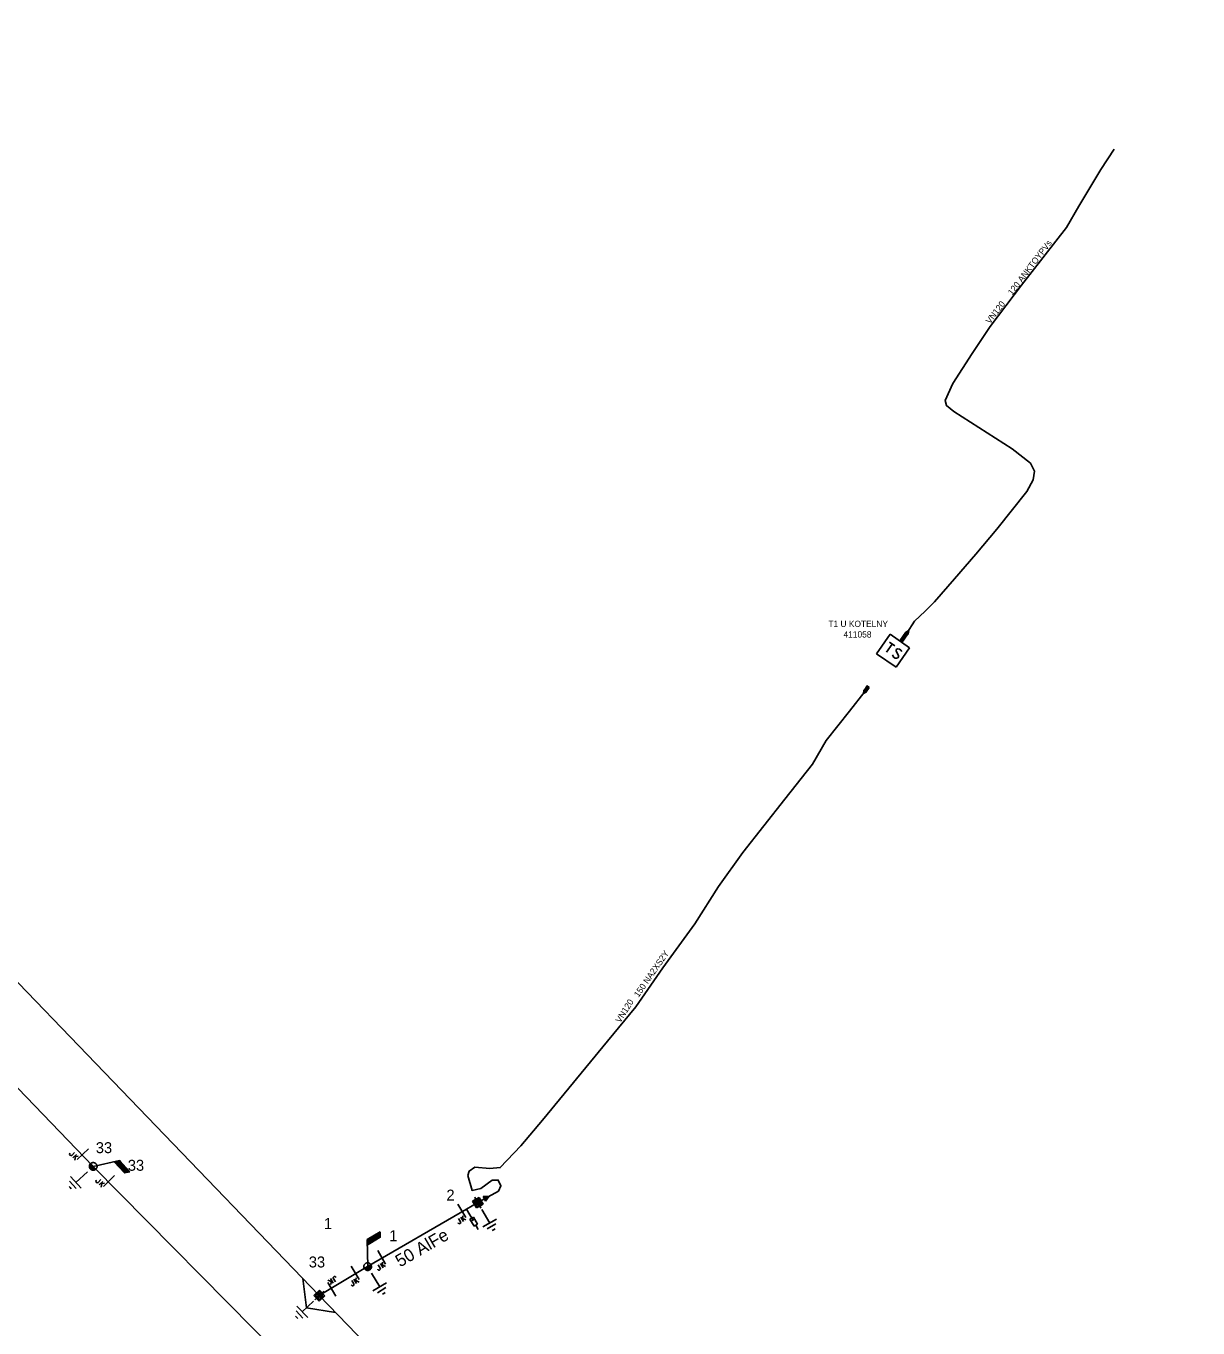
# Model space of a CAD drawing. Extents: x -540340 to -537226, y -1183949 to -1180375.
# Drawn here: x -538950.1 to -538763.3, y -1181558.8 to -1181351.3 of the extents above; entities that cross this region are included whole.
import ezdxf

# ---------------------------------------------------------------- set-up
doc = ezdxf.new("R2010")
doc.units = 0
for name, color, linetype in [('Default', 7, 'Continuous'), ('Vrstva 1', 7, 'Continuous'), ('Vrstva 11', 7, 'Continuous'), ('Vrstva 12', 7, 'Continuous'), ('Vrstva 13', 7, 'Continuous'), ('Vrstva 14', 7, 'Continuous'), ('Vrstva 15', 7, 'Continuous'), ('Vrstva 16', 7, 'Continuous'), ('Vrstva 18', 7, 'Continuous'), ('Vrstva 19', 7, 'Continuous'), ('Vrstva 2', 7, 'Continuous'), ('Vrstva 20', 7, 'Continuous'), ('Vrstva 25', 7, 'Continuous'), ('Vrstva 26', 7, 'Continuous'), ('Vrstva 27', 7, 'Continuous'), ('Vrstva 4', 7, 'Continuous'), ('Vrstva 5', 7, 'Continuous'), ('Vrstva 52', 7, 'Continuous'), ('Vrstva 53', 7, 'Continuous'), ('Vrstva 6', 7, 'Continuous'), ('Vrstva 7', 7, 'Continuous')]:
    doc.layers.add(name, color=color, linetype=linetype)

# ---------------------------------------------------------------- blocks, each defined once
blk = doc.blocks.new('VN840')
at = {"layer": 'Vrstva 15'}
for points in [[(-0.01, 1.41), (-0.01, -1.09)], [(-1.51, -1.24), (-1.51, -1.15)], [(-1.48, -1.35), (-1.51, -1.24)], [(-1.33, -1.42), (-1.48, -1.35)], [(-1.27, -1.42), (-1.33, -1.42)], [(-1.13, -1.35), (-1.27, -1.42)], [(-1.09, -1.24), (-1.13, -1.35)], [(-1.09, -0.59), (-1.09, -1.24)], [(-0.68, -0.59), (-0.68, -1.42)], [(-0.68, -1.11), (-0.27, -0.59)], [(-0.54, -0.94), (-0.2, -1.42)]]:
    blk.add_lwpolyline(points, dxfattribs=at)
blk = doc.blocks.new('VN860')
at = {"layer": 'Vrstva 15'}
for points in [[(-3.74, 0), (0.01, 2.82)], [(0.01, 2.82), (3.76, 0)]]:
    blk.add_lwpolyline(points, dxfattribs=at)
blk = doc.blocks.new('VN440')
at = {"layer": 'Vrstva 2'}
for points in [[(1.22, 0), (1.21, 0.13), (1.19, 0.25), (1.16, 0.38), (1.11, 0.5), (1.05, 0.61), (0.98, 0.72), (0.9, 0.82), (0.81, 0.91), (0.71, 0.99), (0.6, 1.06), (0.49, 1.12), (0.37, 1.16), (0.25, 1.2), (0.12, 1.22), (-0.01, 1.22), (-0.14, 1.22), (-0.26, 1.2), (-0.39, 1.16), (-0.51, 1.12), (-0.62, 1.06), (-0.73, 0.99), (-0.83, 0.91), (-0.92, 0.82), (-1, 0.72), (-1.07, 0.61), (-1.13, 0.5), (-1.18, 0.38), (-1.21, 0.25), (-1.23, 0.13), (-1.24, 0), (-1.23, -0.13), (-1.21, -0.26), (-1.18, -0.38), (-1.13, -0.5), (-1.07, -0.62), (-1, -0.73), (-0.92, -0.83), (-0.83, -0.92), (-0.73, -1), (-0.62, -1.07), (-0.51, -1.13), (-0.39, -1.17), (-0.26, -1.2), (-0.14, -1.23), (-0.01, -1.23), (0.12, -1.23), (0.25, -1.2), (0.37, -1.17), (0.49, -1.13), (0.6, -1.07), (0.71, -1), (0.81, -0.92), (0.9, -0.83), (0.98, -0.73), (1.05, -0.62), (1.11, -0.5), (1.16, -0.38), (1.19, -0.26), (1.21, -0.13), (1.22, 0)], [(-1.24, 0), (1.22, 0)], [(-1.18, -0.34), (1.1, -0.34)], [(-1.01, -0.63), (0.97, -0.63)], [(-0.74, -0.92), (0.68, -0.92)]]:
    blk.add_lwpolyline(points, dxfattribs=at)
blk = doc.blocks.new('VN870')
at = {"layer": 'Vrstva 4'}
for points in [[(0, -0.25), (0.5, 0), (0, 0.25), (-0.5, 0), (0, -0.25)], [(0.37, 0), (0, 0.19), (-0.36, 0), (0, -0.19), (0.37, 0)], [(0.24, 0), (0, 0.12), (-0.25, 0), (0, -0.12), (0.24, 0)], [(0.12, 0), (0, 0.06), (-0.13, 0), (0, -0.06), (0.12, 0)]]:
    blk.add_lwpolyline(points, dxfattribs=at)
blk = doc.blocks.new('VN890')
at = {"layer": 'Vrstva 4'}
for points in [[(-0.41, 0.41), (0.41, 0)], [(-0.41, -0.41), (-0.41, 0.41)], [(0.41, 0), (-0.41, -0.41)], [(-0.34, 0.31), (0.27, 0), (-0.34, -0.3), (-0.34, 0.31)], [(-0.26, 0.2), (0.1, 0), (-0.26, -0.18), (-0.26, 0.2)], [(-0.19, 0.09), (-0.04, 0), (-0.19, -0.08), (-0.19, 0.09)], [(-0.16, -0.01), (-0.16, 0.03), (-0.13, 0.01), (-0.16, -0.01)]]:
    blk.add_lwpolyline(points, dxfattribs=at)
blk = doc.blocks.new('VN820')
at = {"layer": 'Vrstva 13'}
for points in [[(0, 0), (0, -2.1)], [(-0.32, -1.63), (0.34, -1.63)], [(-0.32, -2.95), (-0.32, -1.63)], [(0, -2.1), (-0.12, -1.86)], [(0, -2.1), (0.12, -1.86)], [(0.34, -1.63), (0.34, -2.95)], [(0.34, -2.95), (-0.32, -2.95)], [(0, -2.95), (0, -3.75)]]:
    blk.add_lwpolyline(points, dxfattribs=at)
blk = doc.blocks.new('VN810')
at = {"layer": 'Vrstva 14'}
for points in [[(0, -1.25), (0, -3.75)], [(1.25, -3.75), (-1.25, -3.75)], [(0.77, -4.37), (-0.8, -4.37)], [(0, -5), (-0.25, -5)], [(0.27, -5), (0, -5)]]:
    blk.add_lwpolyline(points, dxfattribs=at)
blk = doc.blocks.new('VN640')
at = {"layer": 'Vrstva 6'}
for points in [[(-1.89, 1.89), (1.89, 1.89)], [(-1.89, -1.89), (-1.89, 1.89)], [(-1.26, 0.79), (-0.22, 0.79)], [(-0.73, 0.79), (-0.73, -0.79)], [(1.2, 0.66), (0.94, 0.79), (0.66, 0.79), (0.41, 0.66), (0.28, 0.47), (0.28, 0.41), (0.41, 0.22), (1.13, -0.16), (1.26, -0.32), (1.26, -0.47), (1.13, -0.66), (0.91, -0.79), (0.63, -0.79), (0.5, -0.73), (0.28, -0.6)], [(1.89, 1.89), (1.89, -1.89)], [(1.89, -1.89), (-1.89, -1.89)]]:
    blk.add_lwpolyline(points, dxfattribs=at)
blk = doc.blocks.new('VN001')
at = {"layer": 'Default'}
for p, q in [((1.73, 3.03), (4.14, 3.03)), ((1.76, 3.08), (4.17, 3.08)), ((1.79, 3.13), (4.2, 3.13)), ((1.82, 3.18), (4.23, 3.18)), ((1.85, 3.23), (4.26, 3.23)), ((1.87, 3.28), (4.29, 3.28)), ((1.9, 3.33), (4.32, 3.33)), ((1.93, 3.38), (4.35, 3.38)), ((1.96, 3.43), (4.37, 3.43)), ((1.99, 3.48), (4.4, 3.48)), ((2.02, 3.53), (4.43, 3.53)), ((2.05, 3.58), (4.46, 3.58)), ((2.07, 3.63), (4.49, 3.63)), ((2.1, 3.68), (4.52, 3.68)), ((2.13, 3.73), (2.54, 3.73))]:
    blk.add_line(p, q, dxfattribs=at)
blk.add_lwpolyline([(2.13, 3.73), (0, 0)], dxfattribs=at)
blk.add_lwpolyline([(4.55, 3.73), (2.13, 3.73), (1.7, 2.98), (4.12, 2.99)], close=True, dxfattribs=at)
blk = doc.blocks.new('VN470')
at = {"layer": 'Vrstva 2'}
for points in [[(-1.23, 1.22), (1.23, 1.22)], [(-1.23, -1.23), (-1.23, 1.22)], [(-0.92, 0.9), (0.92, 0.9)], [(-0.92, -0.95), (-0.92, 0.9)], [(-0.61, 0.61), (0.61, 0.61)], [(-0.61, -0.62), (-0.61, 0.61)], [(-0.31, -0.27), (-0.31, 0.34)], [(-0.31, 0.34), (0.31, 0.34)], [(0, 1.22), (0, 1.97)], [(0.31, 0.34), (0.31, -0.27)], [(0.61, 0.61), (0.61, -0.62)], [(0.92, 0.9), (0.92, -0.95)], [(1.23, 1.22), (1.23, -1.23)], [(1.23, -1.23), (-1.23, -1.23)], [(0.92, -0.95), (-0.92, -0.95)], [(0.61, -0.62), (-0.61, -0.62)], [(0.31, -0.27), (-0.31, -0.27)], [(0, -1.23), (0, -1.98)]]:
    blk.add_lwpolyline(points, dxfattribs=at)

msp = doc.modelspace()

# ---------------------------------------------------------------- linework, layer by layer
at = {"layer": 'Vrstva 1'}
for points in [[(-539146.14, -1181230.44), (-539111.36, -1181296.54), (-539067.4, -1181383.96), (-539015.51, -1181436.9), (-538960.93, -1181493.88), (-538903.36, -1181553.62)], [(-538939.39, -1181533.04), (-538968.73, -1181502.62), (-539023.69, -1181446.75), (-539076.4, -1181392.09), (-539119.1, -1181309.84), (-539155.83, -1181236.81)], [(-538763.29, -1181645.65), (-538807.89, -1181632.52), (-538857.34, -1181618.16), (-538909.5, -1181563.31), (-538939.39, -1181533.04)], [(-538903.36, -1181553.62), (-538849.02, -1181609.88), (-538806.29, -1181621.96)]]:
    msp.add_lwpolyline(points, dxfattribs=at)
at = {"layer": 'Vrstva 20'}
for points in [[(-538809.52, -1181448.13), (-538810.52, -1181449.52), (-538810.84, -1181449.28), (-538809.84, -1181447.89)], [(-538815.7, -1181456.67), (-538816.16, -1181457.37), (-538816.5, -1181457.15), (-538816.04, -1181456.45)]]:
    msp.add_lwpolyline(points, close=True, dxfattribs=at)
at = {"layer": 'Vrstva 5'}
for points in [[(-538809.68, -1181448.01), (-538808.46, -1181446.13), (-538806.8, -1181444.55), (-538805.27, -1181443.02), (-538802.1, -1181439.35), (-538798.72, -1181435.42), (-538795.33, -1181431.47), (-538790.58, -1181425.45), (-538789.58, -1181423.57), (-538789.33, -1181422.23), (-538790, -1181420.95), (-538792.9, -1181418.66), (-538802.22, -1181412.68), (-538803.36, -1181411.75), (-538803.6, -1181410.94), (-538802.39, -1181408.22), (-538799.31, -1181403.45), (-538796.4, -1181399.13), (-538791.4, -1181392.56), (-538784.22, -1181383.36), (-538782.29, -1181379.95), (-538778.77, -1181374.11), (-538776.66, -1181370.87)], [(-538810.68, -1181449.4), (-538809.68, -1181448.01)], [(-538815.87, -1181456.56), (-538816.33, -1181457.26)], [(-538816.33, -1181457.26), (-538818.83, -1181460.47), (-538822.55, -1181465.15), (-538824.73, -1181468.93), (-538829.15, -1181474.51), (-538835.86, -1181482.98), (-538839.73, -1181488.4), (-538843.49, -1181494.37), (-538848.59, -1181501.4), (-538852.89, -1181507.61), (-538857.39, -1181513.06), (-538867.76, -1181525.68), (-538871.21, -1181529.77), (-538874.52, -1181533.23), (-538876.19, -1181533.36), (-538878.57, -1181533.16), (-538879.44, -1181533.78), (-538879.66, -1181534.48), (-538878.99, -1181536.85), (-538877.61, -1181536.54), (-538875.79, -1181535.2), (-538874.82, -1181535.22), (-538874.4, -1181536.13), (-538874.8, -1181536.98), (-538878.07, -1181538.81)]]:
    msp.add_lwpolyline(points, dxfattribs=at)
at = {"layer": 'Vrstva 52'}
for points in [[(-538895.65, -1181549), (-538879.89, -1181539.86), (-538878.07, -1181538.81)], [(-538903.36, -1181553.62), (-538895.65, -1181549)]]:
    msp.add_lwpolyline(points, dxfattribs=at)

# ---------------------------------------------------------------- block references
at = {"layer": 'Vrstva 11'}
for p, rotation in [((-538939.39, -1181533.04), -47.51486941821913), ((-538895.64, -1181549), 30.9234250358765)]:
    msp.add_blockref('VN001', p, dxfattribs=dict(at, rotation=rotation))
at = {"layer": 'Vrstva 13'}
for name, p, xscale, yscale, rotation in [('VN440', (-538939.39, -1181533.04), 0.5, 0.5, -46.02819990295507), ('VN470', (-538878.08, -1181538.81), 0.49999999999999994, 0.5000000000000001, 30.104105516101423), ('VN440', (-538895.64, -1181549), 0.5, 0.5, 30.92627499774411), ('VN470', (-538903.36, -1181553.62), 0.49999999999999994, 0.5000000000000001, -46.05909170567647)]:
    msp.add_blockref(name, p, dxfattribs=dict(at, xscale=xscale, yscale=yscale, rotation=rotation))
at = {"layer": 'Vrstva 15'}
for p, rotation in [((-538939.39, -1181533.04), -47.51486946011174), ((-538878.07, -1181538.81), 30.103616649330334), ((-538895.65, -1181549), 30.925158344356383), ((-538903.36, -1181553.62), -46.05909170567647)]:
    msp.add_blockref('VN810', p, dxfattribs=dict(at, rotation=rotation))
at = {"layer": 'Vrstva 16', "rotation": 29.970630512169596}
msp.add_blockref('VN820', (-538879.89, -1181539.86), dxfattribs=at)
at = {"layer": 'Vrstva 18'}
for name, p, rotation in [('VN840', (-538941.17, -1181531.19), -46.02845558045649), ('VN840', (-538936.98, -1181535.48), -45.36669446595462), ('VN840', (-538880.54, -1181540.24), 31.088291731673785), ('VN840', (-538893.32, -1181547.65), 30.094086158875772), ('VN840', (-538897.56, -1181550.14), 30.92443332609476), ('VN860', (-538903.36, -1181553.62), 133.94076106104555), ('VN840', (-538901.43, -1181552.48), -149.5046360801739)]:
    msp.add_blockref(name, p, dxfattribs=dict(at, rotation=rotation))
at = {"layer": 'Vrstva 19'}
for name, p, rotation in [('VN870', (-538809.68, -1181448.01), -125.7321637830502), ('VN870', (-538816.33, -1181457.26), 56.68936909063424), ('VN890', (-538876.68, -1181538), 28.35887503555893)]:
    msp.add_blockref(name, p, dxfattribs=dict(at, rotation=rotation))
at = {"layer": 'Vrstva 25', "rotation": -34.64668053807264}
msp.add_blockref('VN640', (-538811.88, -1181450.84), dxfattribs=at)

# ---------------------------------------------------------------- texts
at = {"layer": 'Vrstva 12'}
for s, p in [('33', (-538933.88, -1181533.73)), ('1', (-538902.63, -1181543.02))]:
    msp.add_text(s, height=1.75, dxfattribs=at).set_placement(p)
at = {"layer": 'Vrstva 14'}
for s, p in [('33', (-538938.98, -1181530.92)), ('2', (-538883.09, -1181538.48)), ('1', (-538892.2, -1181544.95)), ('33', (-538905.03, -1181549.14))]:
    msp.add_text(s, height=1.75, dxfattribs=at).set_placement(p)
at = {"layer": 'Vrstva 26'}
msp.add_text('411058', height=1, dxfattribs=at).set_placement((-538819.79, -1181448.73))
at = {"layer": 'Vrstva 27'}
msp.add_text('T1 U KOTELNY', height=1, dxfattribs=at).set_placement((-538822.21, -1181447.05))
at = {"layer": 'Vrstva 53'}
msp.add_text('50 AlFe', height=2, rotation=30.094, dxfattribs=at).set_placement((-538890.49, -1181549.16))
at = {"layer": 'Vrstva 6'}
for s, rotation, p in [('120 ANKTOYPVs', 52.754, (-538792.9, -1181394.27)), ('150 NA2XS2Y', 55.302, (-538852.46, -1181506.16))]:
    msp.add_text(s, height=1, rotation=rotation, dxfattribs=at).set_placement(p)
at = {"layer": 'Vrstva 7'}
for rotation, p in [(52.754, (-538796.42, -1181398.83)), (57.779, (-538855.37, -1181510.24))]:
    msp.add_text('VN120', height=1, rotation=rotation, dxfattribs=at).set_placement(p)

doc.saveas('drawing.dxf')
